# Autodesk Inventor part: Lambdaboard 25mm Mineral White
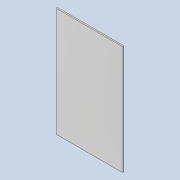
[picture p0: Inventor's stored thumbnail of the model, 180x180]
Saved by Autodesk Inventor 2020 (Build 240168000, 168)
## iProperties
Created: 2020-11
Part Number: Lambdaboard 25mm Mineral White
Material: Generic
Document SubType Name: Modeling
Designer: Yolande
Density: 1 g/cm^3
Appearance: Smooth - White
Description: Lambdaboard 25mm Mineral White
description: 0:0:Lambdaboard 25mm W/M
manufacturer: 0:0:Lambdaboard T/A Rigifoam
model: 0:0:
url: 0:0:www.lambdaboard.co.za
Author: Yolande
Title: Lambdaboard 25mm Mineral White
Revision Number: 0
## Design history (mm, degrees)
derived "Lambdaboard 25mm.iam"
body "Solid1"
node "Lambdaboard 25mm BIM.ipt:1" dims "d0" = 10
